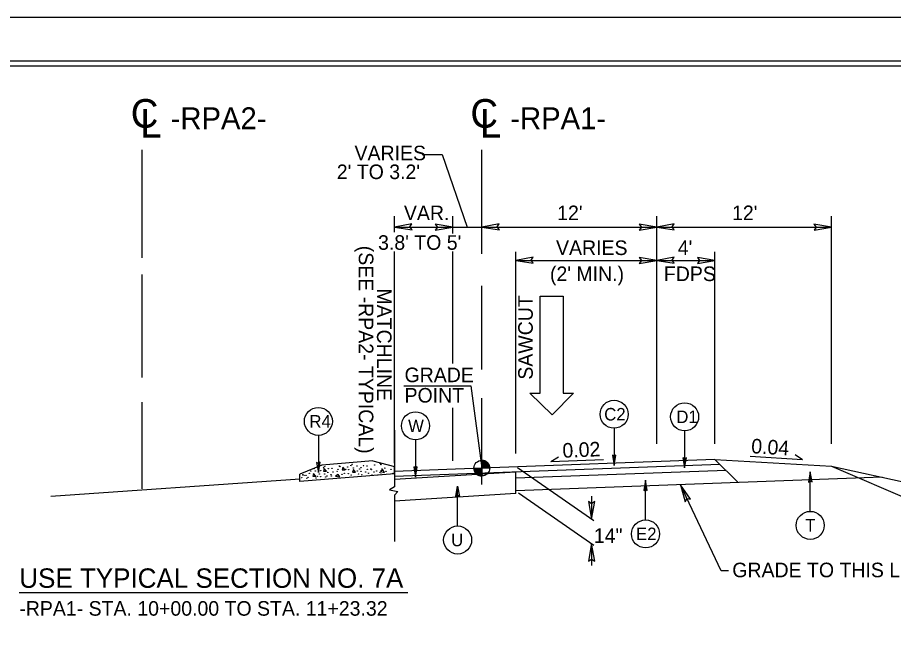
# Model space of a CAD drawing. Extents: x 573748 to 574632, y -54663 to -53209.
# Drawn here: x 574020.2 to 574110.4, y -53976.7 to -53913.7 of the extents above; entities that cross this region are included whole.
import ezdxf

# ---------------------------------------------------------------- set-up
doc = ezdxf.new("R2010")
doc.units = 0
for name, color, linetype in [('Prop Dimension', 7, 'Continuous'), ('Prop Dimension Text', 7, 'Continuous'), ('Prop Lane Arrow CELL', 7, 'Continuous'), ('Prop Terminator CELL', 7, 'Continuous'), ('Sheet Cutting Line CELL', 7, 'Continuous'), ('Sheet Plot Border Inside CELL', 7, 'Continuous'), ('Sheet Plot Border Outside CELL', 7, 'Continuous'), ('Sheet Typical CELL', 7, 'Continuous'), ('Typical Arrow Superelevation CELL', 7, 'Continuous'), ('Typical Curb CELL', 7, 'Continuous'), ('Typical Grade Point Symbol CELL', 7, 'Continuous'), ('Typical Hinge Slope Arterial CELL', 7, 'Continuous'), ('Typical ID Circle CELL', 7, 'Continuous'), ('Typical Pavement Slope CELL', 7, 'Continuous'), ('Typical Terminator CELL', 7, 'Continuous'), ('Typical Text Centerline CELL', 7, 'Continuous'), ('Typical Text General CELL', 7, 'Continuous'), ('Typical Text ID Circle CELL', 7, 'Continuous')]:
    doc.layers.add(name, color=color, linetype=linetype)

# ---------------------------------------------------------------- blocks, each defined once
blk = doc.blocks.new('CENTERLINE TEXT CL')
at = {"layer": 'Typical Text Centerline CELL'}
blk.add_text('C', height=1.64, dxfattribs=at).set_placement((-0.546, -0.261))
blk.add_text('L', height=1.641, rotation=359.9469, dxfattribs=at).set_placement((-0.001, -0.821))

msp = doc.modelspace()

# ---------------------------------------------------------------- linework, layer by layer
at = {"layer": 'Prop Dimension'}
for p, q in [((574033.069, -53938.42), (574033.069, -53927.287)), ((574068.031, -53938.005), (574068.031, -53927.287)), ((574059.031, -53935.759), (574059.031, -53934.12)), ((574065.031, -53935.925), (574065.031, -53934.12)), ((574086.031, -53957.575), (574086.031, -53934.12)), ((574104.031, -53957.575), (574104.031, -53934.12)), ((574059.031, -53935.25), (574065.031, -53935.25)), ((574065.031, -53935.25), (574068.031, -53935.25)), ((574068.031, -53935.25), (574086.031, -53935.25)), ((574086.031, -53935.25), (574104.031, -53935.25)), ((574059.031, -53959.565), (574059.031, -53937.768)), ((574065.031, -53949.298), (574065.031, -53937.768)), ((574071.517, -53958.545), (574071.517, -53937.788)), ((574092.031, -53957.575), (574092.031, -53937.788)), ((574071.517, -53938.676), (574086.031, -53938.676)), ((574086.031, -53938.676), (574092.031, -53938.676)), ((574033.069, -53950.744), (574033.069, -53940.145)), ((574068.031, -53949.904), (574068.031, -53941.285)), ((574033.069, -53962.183), (574033.069, -53953.277)), ((574068.031, -53961.768), (574068.031, -53952.862)), ((574065.031, -53959.312), (574065.031, -53953.854)), ((574059.031, -53956.172), (574059.031, -53961.994)), ((574071.517, -53960.471), (574059.031, -53961.256)), ((574071.709, -53960.013), (574079.555, -53965.466)), ((574059.031, -53961.994), (574058.526, -53962.29)), ((574058.526, -53962.29), (574059.391, -53962.487)), ((574059.391, -53962.487), (574059.031, -53962.838)), ((574071.517, -53962.678), (574071.517, -53962.411)), ((574071.517, -53962.678), (574059.031, -53963.463)), ((574059.031, -53962.838), (574059.031, -53967.634)), ((574071.789, -53962.6), (574079.555, -53967.997)), ((574079.337, -53962.965), (574079.337, -53965.314)), ((574079.337, -53967.845), (574079.337, -53970.1))]:
    msp.add_line(p, q, dxfattribs=at)
for points in [[(574061.895, -53927.777), (574063.943, -53927.777), (574066.531, -53935.25)], [(574060.005, -53951.581), (574066.894, -53951.581), (574068.031, -53960.072)], [(574093.408, -53970.66), (574092.659, -53970.66), (574088.48, -53961.776)]]:
    msp.add_lwpolyline(points, dxfattribs=at)
at = {"layer": 'Prop Lane Arrow CELL'}
for p, q in [((574074.044, -53952.34), (574074.044, -53942.365)), ((574074.044, -53942.365), (574076.395, -53942.365)), ((574076.395, -53942.365), (574076.395, -53952.34)), ((574075.255, -53954.584), (574072.975, -53952.34)), ((574072.975, -53952.34), (574074.044, -53952.34)), ((574077.464, -53952.34), (574075.255, -53954.584)), ((574076.395, -53952.34), (574077.464, -53952.34))]:
    msp.add_line(p, q, dxfattribs=at)
at = {"layer": 'Prop Terminator CELL'}
for points in [[(574060.828, -53934.917), (574059.031, -53935.25), (574060.846, -53935.547), (574060.612, -53935.23)], [(574063.235, -53935.583), (574065.031, -53935.25), (574063.217, -53934.953), (574063.451, -53935.27)], [(574069.828, -53934.917), (574068.031, -53935.25), (574069.846, -53935.547), (574069.612, -53935.23)], [(574084.235, -53935.583), (574086.031, -53935.25), (574084.217, -53934.953), (574084.451, -53935.27)], [(574087.828, -53934.917), (574086.031, -53935.25), (574087.846, -53935.547), (574087.612, -53935.23)], [(574102.235, -53935.583), (574104.031, -53935.25), (574102.217, -53934.953), (574102.451, -53935.27)], [(574073.314, -53938.343), (574071.517, -53938.676), (574073.332, -53938.973), (574073.098, -53938.656)], [(574084.235, -53939.009), (574086.031, -53938.676), (574084.217, -53938.379), (574084.451, -53938.696)], [(574087.828, -53938.343), (574086.031, -53938.676), (574087.846, -53938.973), (574087.612, -53938.656)], [(574090.235, -53939.009), (574092.031, -53938.676), (574090.217, -53938.379), (574090.451, -53938.696)], [(574089.527, -53963.274), (574088.48, -53961.776), (574088.961, -53963.551), (574089.153, -53963.207)], [(574079.027, -53963.514), (574079.337, -53965.314), (574079.657, -53963.504), (574079.337, -53963.734)], [(574079.647, -53969.646), (574079.337, -53967.845), (574079.017, -53969.656), (574079.337, -53969.426)]]:
    msp.add_lwpolyline(points, close=True, dxfattribs=at)
at = {"layer": 'Sheet Cutting Line CELL'}
msp.add_line((574280.971, -53913.672), (573944.171, -53913.672), dxfattribs=at)
at = {"layer": 'Sheet Plot Border Inside CELL'}
msp.add_lwpolyline([(574280.071, -53918.162), (573946.771, -53918.162), (573946.771, -54129.182), (574280.071, -54129.182)], close=True, dxfattribs=at)
at = {"layer": 'Sheet Plot Border Outside CELL'}
msp.add_lwpolyline([(574280.971, -53913.672), (573944.171, -53913.672), (573944.171, -54133.672), (574280.971, -54133.672)], close=True, dxfattribs=at)
at = {"layer": 'Sheet Typical CELL'}
msp.add_lwpolyline([(574277.571, -53918.672), (573977.571, -53918.672), (573977.571, -54128.672), (574277.571, -54128.672)], close=True, dxfattribs=at)
at = {"layer": 'Typical Arrow Superelevation CELL'}
for p, q in [((574101.04, -53959.198), (574095.656, -53958.863)), ((574101.04, -53959.198), (574100.277, -53958.692)), ((574075.15, -53959.397), (574075.922, -53958.907)), ((574075.15, -53959.397), (574080.539, -53959.173))]:
    msp.add_line(p, q, dxfattribs=at)
at = {"layer": 'Typical Curb CELL'}
for p, q in [((574051.579, -53959.747), (574049.285, -53960.68)), ((574056.804, -53959.323), (574051.579, -53959.747)), ((574056.804, -53959.323), (574059.03, -53959.907)), ((574049.286, -53961.456), (574049.285, -53960.68)), ((574059.031, -53960.666), (574049.286, -53961.456)), ((574050.713, -53960.615), (574050.636, -53960.891)), ((574050.938, -53960.893), (574050.713, -53960.615)), ((574051.818, -53960.101), (574051.741, -53960.378)), ((574051.741, -53960.378), (574052.043, -53960.38)), ((574052.043, -53960.38), (574051.818, -53960.101)), ((574053.737, -53959.971), (574053.66, -53960.247)), ((574053.66, -53960.247), (574053.962, -53960.249)), ((574053.962, -53960.249), (574053.737, -53959.971)), ((574054.805, -53960.21), (574054.729, -53960.486)), ((574054.729, -53960.486), (574055.03, -53960.488)), ((574055.03, -53960.488), (574054.805, -53960.21)), ((574057.84, -53960.234), (574057.589, -53960.425)), ((574057.589, -53960.425), (574058.005, -53960.503)), ((574058.005, -53960.503), (574057.84, -53960.234)), ((574059.031, -53960.666), (574059.03, -53959.907)), ((574050.636, -53960.891), (574050.938, -53960.893)), ((574053.234, -53960.712), (574052.983, -53960.903)), ((574052.983, -53960.903), (574053.399, -53960.98)), ((574053.399, -53960.98), (574053.234, -53960.712))]:
    msp.add_line(p, q, dxfattribs=at)
for centre in [(574054.558, -53959.798), (574054.686, -53959.691), (574056.99, -53959.756), (574057.586, -53959.617), (574057.645, -53959.701), (574050.285, -53960.591), (574050.43, -53960.355), (574050.77, -53960.111), (574050.901, -53960.363), (574051.298, -53960.669), (574051.435, -53960.327), (574051.736, -53960.03), (574051.865, -53959.922), (574051.868, -53960.677), (574052.175, -53960.518), (574052.223, -53960.126), (574052.612, -53960.082), (574052.706, -53960.472), (574053.132, -53960.412), (574053.217, -53960.183), (574053.364, -53959.846), (574053.423, -53959.929), (574053.636, -53960.716), (574053.871, -53960.595), (574054.03, -53960.182), (574054.214, -53959.964), (574054.277, -53960.633), (574054.323, -53960.241), (574054.801, -53960.053), (574055.185, -53959.856), (574055.215, -53960.373), (574055.332, -53960.66), (574055.469, -53960.167), (574055.581, -53960.02), (574055.592, -53960.399), (574055.849, -53959.828), (574056.072, -53960.476), (574056.209, -53959.845), (574056.236, -53960.191), (574056.37, -53960.587), (574056.604, -53960.145), (574056.664, -53960.229), (574056.929, -53960.452), (574057.212, -53960.374), (574057.553, -53960.495), (574057.751, -53960.151), (574058.033, -53960.073), (574058.16, -53960.399), (574058.672, -53960.203), (574058.879, -53960.612), (574049.499, -53961.039), (574049.606, -53960.757), (574049.733, -53960.825), (574049.922, -53960.812), (574050.014, -53961.112), (574050.151, -53961.025), (574050.956, -53961.079), (574051.089, -53960.918), (574051.441, -53960.953), (574051.96, -53960.978), (574052.097, -53960.89), (574052.519, -53960.74), (574052.553, -53960.89), (574054.579, -53960.769), (574055.671, -53960.753), (574056.73, -53960.78), (574057.299, -53960.789)]:
    msp.add_ellipse(centre, major_axis=(-0.0198, -0.0031), ratio=0.961441, dxfattribs=at)
msp.add_ellipse((574057.655, -53960.67), major_axis=(0.0225, 0.0035), ratio=0.961441, start_param=0.356987, end_param=2.577098, dxfattribs=at)
at = {"layer": 'Typical Grade Point Symbol CELL'}
for p, q in [((574068.031, -53960.072), (574068.031, -53959.266)), ((574067.226, -53960.072), (574068.031, -53960.072)), ((574068.029, -53960.877), (574068.031, -53960.072)), ((574068.031, -53960.072), (574068.029, -53960.877)), ((574068.837, -53960.072), (574068.031, -53960.072))]:
    msp.add_line(p, q, dxfattribs=at)
for points in [[(574068.038, -53959.266), (574068.038, -53959.266), (574068.038, -53960.072)], [(574068.055, -53959.266), (574068.055, -53960.072)], [(574068.071, -53959.268), (574068.071, -53960.072)], [(574068.087, -53959.268), (574068.087, -53960.072)], [(574068.103, -53959.27), (574068.103, -53960.072)], [(574068.119, -53959.271), (574068.119, -53960.072)], [(574068.135, -53959.273), (574068.135, -53960.072)], [(574068.151, -53959.275), (574068.151, -53960.072)], [(574068.167, -53959.277), (574068.167, -53960.072)], [(574068.183, -53959.28), (574068.183, -53960.072)], [(574068.2, -53959.284), (574068.2, -53960.072)], [(574068.216, -53959.288), (574068.216, -53960.072)], [(574068.232, -53959.291), (574068.232, -53960.072)], [(574068.248, -53959.296), (574068.248, -53960.072)], [(574068.264, -53959.3), (574068.264, -53960.072)], [(574068.28, -53959.305), (574068.28, -53960.072)], [(574068.296, -53959.311), (574068.296, -53960.072)], [(574068.312, -53959.316), (574068.312, -53960.072)], [(574068.328, -53959.323), (574068.328, -53960.072)], [(574068.345, -53959.33), (574068.345, -53960.072)], [(574068.361, -53959.338), (574068.361, -53960.072)], [(574068.377, -53959.345), (574068.377, -53960.072)], [(574068.393, -53959.352), (574068.393, -53960.072)], [(574068.409, -53959.361), (574068.409, -53960.072)], [(574068.425, -53959.37), (574068.425, -53960.072)], [(574068.441, -53959.379), (574068.441, -53960.072)], [(574068.457, -53959.388), (574068.457, -53960.072)], [(574068.473, -53959.399), (574068.473, -53960.072)], [(574068.49, -53959.409), (574068.49, -53960.072)], [(574068.506, -53959.422), (574068.506, -53960.072)], [(574068.522, -53959.433), (574068.522, -53960.072)], [(574068.538, -53959.445), (574068.538, -53960.072)], [(574068.554, -53959.459), (574068.554, -53960.072)], [(574068.57, -53959.474), (574068.57, -53960.072)], [(574068.586, -53959.488), (574068.586, -53960.072)], [(574068.602, -53959.504), (574068.602, -53960.072)], [(574068.618, -53959.52), (574068.618, -53960.072)], [(574068.635, -53959.538), (574068.635, -53960.072)], [(574068.651, -53959.558), (574068.651, -53960.072)], [(574068.667, -53959.578), (574068.667, -53960.072)], [(574068.683, -53959.599), (574068.683, -53960.072)], [(574068.699, -53959.622), (574068.699, -53960.072)], [(574068.715, -53959.647), (574068.715, -53960.072)], [(574068.731, -53959.674), (574068.731, -53960.072)], [(574068.747, -53959.703), (574068.747, -53960.072)], [(574068.763, -53959.737), (574068.763, -53960.072)], [(574068.78, -53959.775), (574068.78, -53960.072)], [(574067.229, -53960.072), (574067.229, -53960.159)], [(574067.245, -53960.072), (574067.245, -53960.254)], [(574067.261, -53960.072), (574067.261, -53960.312)], [(574067.277, -53960.072), (574067.277, -53960.36)], [(574067.294, -53960.072), (574067.294, -53960.398)], [(574067.31, -53960.072), (574067.31, -53960.432)], [(574067.326, -53960.072), (574067.326, -53960.462)], [(574067.342, -53960.072), (574067.342, -53960.491)], [(574067.358, -53960.072), (574067.358, -53960.516)], [(574067.374, -53960.072), (574067.374, -53960.539)], [(574067.39, -53960.072), (574067.39, -53960.56)], [(574067.406, -53960.072), (574067.406, -53960.58)], [(574067.423, -53960.072), (574067.423, -53960.6)], [(574067.439, -53960.072), (574067.439, -53960.618)], [(574067.455, -53960.072), (574067.455, -53960.636)], [(574067.471, -53960.072), (574067.471, -53960.652)], [(574067.487, -53960.072), (574067.487, -53960.666)], [(574067.503, -53960.072), (574067.503, -53960.68)], [(574067.519, -53960.072), (574067.519, -53960.695)], [(574067.535, -53960.072), (574067.535, -53960.707)], [(574067.551, -53960.072), (574067.551, -53960.72)], [(574067.568, -53960.072), (574067.568, -53960.731)], [(574067.584, -53960.072), (574067.584, -53960.741)], [(574067.6, -53960.072), (574067.6, -53960.752)], [(574067.616, -53960.072), (574067.616, -53960.763)], [(574067.632, -53960.072), (574067.632, -53960.772)], [(574067.648, -53960.072), (574067.648, -53960.781)], [(574067.664, -53960.072), (574067.664, -53960.79)], [(574067.68, -53960.072), (574067.68, -53960.797)], [(574067.696, -53960.072), (574067.696, -53960.804)], [(574067.713, -53960.072), (574067.713, -53960.811)], [(574067.729, -53960.072), (574067.729, -53960.818)], [(574067.745, -53960.072), (574067.745, -53960.825)], [(574067.761, -53960.072), (574067.761, -53960.831)], [(574067.777, -53960.072), (574067.777, -53960.836)], [(574067.793, -53960.072), (574067.793, -53960.842)], [(574067.809, -53960.072), (574067.809, -53960.845)], [(574067.825, -53960.072), (574067.825, -53960.851)], [(574067.842, -53960.072), (574067.842, -53960.854)], [(574067.858, -53960.072), (574067.858, -53960.858)], [(574067.874, -53960.072), (574067.874, -53960.861)], [(574067.89, -53960.072), (574067.89, -53960.865)], [(574067.906, -53960.072), (574067.906, -53960.867)], [(574067.922, -53960.072), (574067.922, -53960.87)], [(574067.938, -53960.072), (574067.938, -53960.872)], [(574067.954, -53960.072), (574067.954, -53960.874)], [(574067.97, -53960.072), (574067.97, -53960.876)], [(574067.987, -53960.072), (574067.987, -53960.876)], [(574068.003, -53960.072), (574068.003, -53960.877)], [(574068.019, -53960.072), (574068.019, -53960.877), (574068.019, -53960.877)], [(574068.796, -53959.819), (574068.796, -53960.072)], [(574068.812, -53959.875), (574068.812, -53960.072)], [(574068.828, -53959.957), (574068.828, -53960.072)]]:
    msp.add_lwpolyline(points, dxfattribs=at)
msp.add_circle((574068.03, -53960.072), 0.806, dxfattribs=at)
for start, end in [(359.99048, 89.99048), (179.99048, 269.99048)]:
    msp.add_arc((574068.03, -53960.072), 0.806, start, end, dxfattribs=at)
at = {"layer": 'Typical Hinge Slope Arterial CELL'}
for q in [(574143.131, -53968.376), (574142.42, -53976.388)]:
    msp.add_line((574104.031, -53959.871), q, dxfattribs=at)
at = {"layer": 'Typical ID Circle CELL'}
for p, q in [((574081.647, -53955.964), (574081.647, -53959.791)), ((574051.205, -53956.702), (574051.205, -53960.528)), ((574088.905, -53956.227), (574088.905, -53960.053)), ((574061.204, -53957.155), (574061.204, -53960.982)), ((574101.837, -53964.521), (574101.837, -53960.438)), ((574084.884, -53965.399), (574084.884, -53961.316)), ((574065.541, -53966.026), (574065.541, -53961.942))]:
    msp.add_line(p, q, dxfattribs=at)
for centre in [(574081.647, -53954.522), (574088.905, -53954.784), (574051.204, -53955.259), (574061.204, -53955.713), (574101.837, -53965.964), (574065.541, -53967.468), (574084.884, -53966.842)]:
    msp.add_circle(centre, 1.443, dxfattribs=at)
at = {"layer": 'Typical Pavement Slope CELL'}
for p, q in [((574092.545, -53959.684), (574059.031, -53960.938)), ((574092.031, -53959.174), (574068.031, -53960.072)), ((574092.031, -53959.174), (574104.031, -53959.871)), ((574094.427, -53961.554), (574092.031, -53959.174)), ((574068.031, -53960.072), (574059.031, -53960.408)), ((574093.169, -53960.304), (574071.517, -53961.115)), ((574071.517, -53962.411), (574071.517, -53960.471)), ((574048.344, -53961.265), (574023.656, -53962.983)), ((574049.286, -53961.199), (574048.344, -53961.265)), ((574109.225, -53961), (574071.517, -53962.411))]:
    msp.add_line(p, q, dxfattribs=at)
at = {"layer": 'Typical Terminator CELL'}
for points in [[(574081.465, -53958.736), (574081.647, -53959.791), (574081.834, -53958.73), (574081.647, -53958.865)], [(574051.023, -53959.474), (574051.205, -53960.528), (574051.392, -53959.468), (574051.205, -53959.603)], [(574088.723, -53958.999), (574088.905, -53960.053), (574089.093, -53958.993), (574088.905, -53959.128)], [(574061.023, -53959.927), (574061.204, -53960.982), (574061.392, -53959.921), (574061.204, -53960.056)], [(574102.019, -53961.492), (574101.837, -53960.438), (574101.649, -53961.498), (574101.837, -53961.363)], [(574085.065, -53962.37), (574084.884, -53961.316), (574084.696, -53962.376), (574084.884, -53962.241)], [(574065.359, -53962.997), (574065.541, -53961.942), (574065.728, -53963.003), (574065.541, -53962.868)]]:
    msp.add_lwpolyline(points, close=True, dxfattribs=at)
at = {"layer": 'Typical Text General CELL'}
msp.add_line((574020.421, -53972.89), (574060.414, -53972.89), dxfattribs=at)

# ---------------------------------------------------------------- block references
at = {"layer": 'Prop Dimension', "xscale": 1.8000000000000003, "yscale": 1.8000000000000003}
for p in [(574032.872, -53924.553), (574067.835, -53924.553)]:
    msp.add_blockref('CENTERLINE TEXT CL', p, dxfattribs=at)

# ---------------------------------------------------------------- texts
at = {"layer": 'Prop Dimension'}
msp.add_text('-RPA2-', height=2.25, dxfattribs=at).set_placement((574036, -53925.17))
msp.add_text('GRADE TO THIS LINE', height=1.5, rotation=360, dxfattribs=at).set_placement((574093.812, -53971.304))
at = {"layer": 'Prop Dimension Text'}
for s, height, p in [('-RPA1-', 2.25, (574070.962, -53925.17)), ('VARIES', 1.5, (574054.929, -53928.372)), ("2' TO 3.2'", 1.5, (574053.101, -53930.307)), ('VAR.', 1.5, (574060.013, -53934.534)), ("12'", 1.5, (574075.787, -53934.534)), ("12'", 1.5, (574093.787, -53934.534)), ("3.8' TO 5'", 1.5, (574057.35, -53937.588)), ('VARIES', 1.5, (574075.671, -53938.127)), ("4'", 1.5, (574088.2, -53938.127)), ("(2' MIN.)", 1.5, (574075.044, -53940.808)), ('FDPS', 1.5, (574086.772, -53940.808)), ('GRADE', 1.5, (574060.076, -53951.218)), ('POINT', 1.5, (574060.076, -53953.318)), ('14"', 1.5, (574079.566, -53967.764))]:
    msp.add_text(s, height=height, dxfattribs=at).set_placement(p)
for s, rotation, p in [('(SEE -RPA2- TYPICAL)', 270, (574055.364, -53937.174)), ('MATCHLINE', 270, (574057.237, -53941.572)), ('SAWCUT', 90, (574073.276, -53950.959)), ('0.04', 356.43884, (574095.728, -53958.524)), ('0.02', 2.37567, (574076.36, -53959.004))]:
    msp.add_text(s, height=1.5, rotation=rotation, dxfattribs=at).set_placement(p)
at = {"layer": 'Typical Text General CELL'}
for s, height, p in [('USE TYPICAL SECTION NO. 7A', 2, (574020.421, -53972.393)), ('-RPA1- STA. 10+00.00 TO STA. 11+23.32', 1.5, (574020.421, -53975.263))]:
    msp.add_text(s, height=height, dxfattribs=at).set_placement(p)
at = {"layer": 'Typical Text ID Circle CELL'}
for s, height, p in [('C2', 1.2912, (574080.626, -53955.164)), ('D1', 1.2912, (574088.05, -53955.427)), ('R4', 1.2912, (574050.282, -53955.902)), ('W', 1.291, (574060.437, -53956.355)), ('T', 1.291, (574101.315, -53966.607)), ('U', 1.291, (574064.87, -53968.111)), ('E2', 1.2912, (574083.902, -53967.485))]:
    msp.add_text(s, height=height, dxfattribs=at).set_placement(p)

doc.saveas('drawing.dxf')
